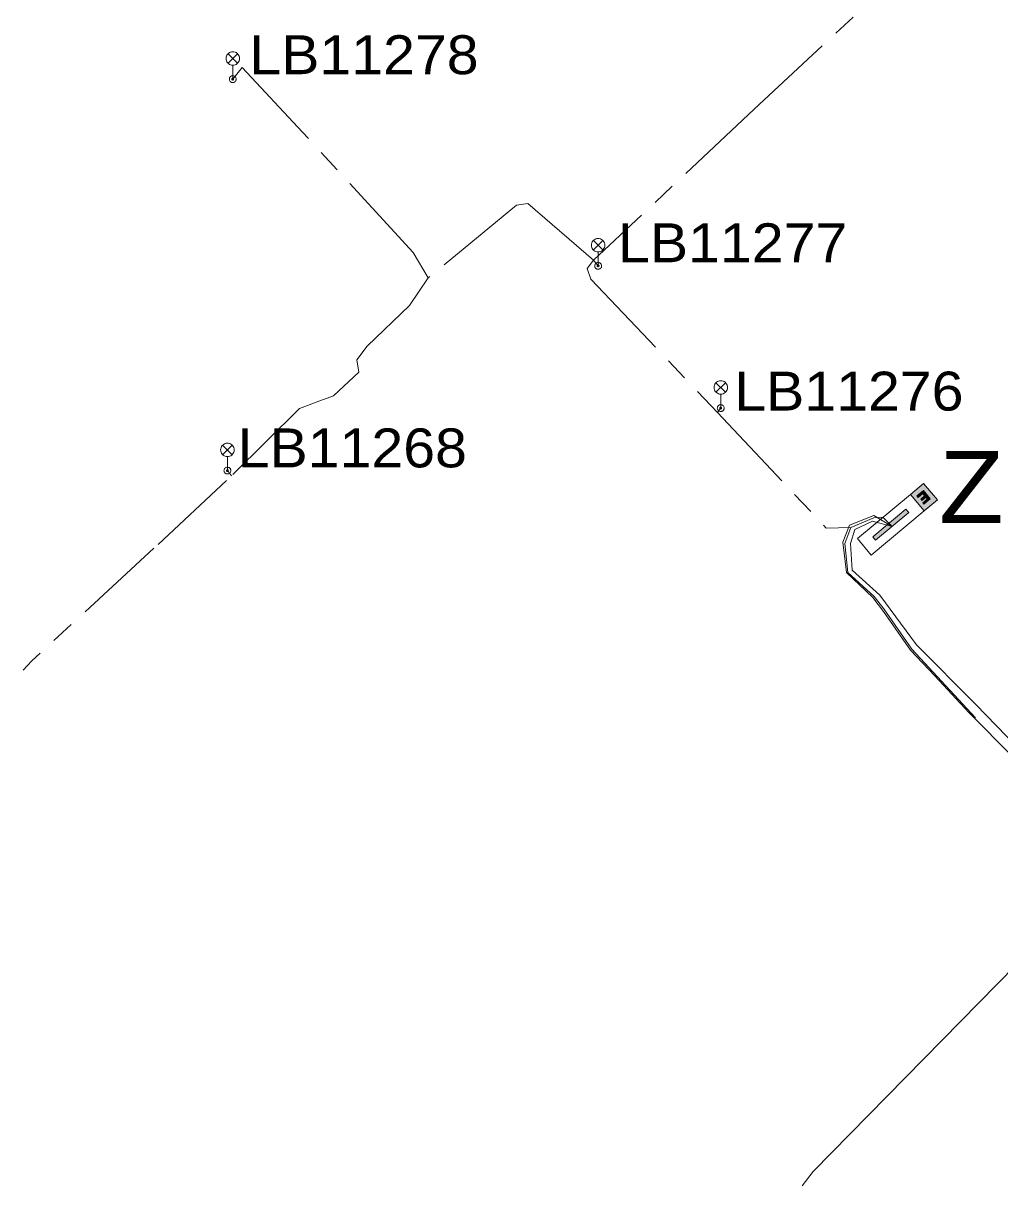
# Model space of a CAD drawing. Extents: x -688049 to -687261, y -973611 to -973038.
# Drawn here: x -687618.8 to -687564.4, y -973611.3 to -973546.5 of the extents above; entities that cross this region are included whole.
import ezdxf

# ---------------------------------------------------------------- set-up
doc = ezdxf.new("R2010")
doc.units = 0
doc.header["$LTSCALE"] = 0.87
doc.linetypes.add('LONG_DASH_SHORT_DASH', pattern=[9.9, 6, -1.2, 1.5, -1.2])
doc.layers.add('1', color=7, linetype='Continuous', lineweight=13)

msp = doc.modelspace()

# ---------------------------------------------------------------- hatches: boundary and pattern name
at = {"layer": '1'}
for points in [[(-687567.892, -973573.083), (-687568.629, -973573.698), (-687569.398, -973572.777), (-687568.661, -973572.162)], [(-687568.673, -973572.563), (-687568.289, -973573.023), (-687568.644, -973573.32), (-687568.708, -973573.244), (-687568.458, -973573.034), (-687568.542, -973572.933), (-687568.76, -973573.115), (-687568.823, -973573.038), (-687568.606, -973572.857), (-687568.708, -973572.734), (-687568.959, -973572.943), (-687569.029, -973572.859)], [(-687569.489, -973573.791), (-687571.332, -973575.329), (-687571.485, -973575.145), (-687569.643, -973573.607)]]:
    msp.add_hatch(color=256, dxfattribs=at).paths.add_polyline_path(points)

# ---------------------------------------------------------------- linework, layer by layer
for p, q in [((-687607.405, -973548.235), (-687606.875, -973548.765)), ((-687607.405, -973548.765), (-687606.875, -973548.235)), ((-687607.14, -973549.65), (-687607.14, -973548.875)), ((-687587.055, -973558.635), (-687586.525, -973559.165)), ((-687587.055, -973559.165), (-687586.525, -973558.635)), ((-687586.79, -973560.05), (-687586.79, -973559.275)), ((-687580.225, -973566.555), (-687579.695, -973567.085)), ((-687580.225, -973567.085), (-687579.695, -973566.555)), ((-687579.96, -973567.97), (-687579.96, -973567.195)), ((-687607.705, -973570.035), (-687607.175, -973570.565)), ((-687607.705, -973570.565), (-687607.175, -973570.035)), ((-687607.44, -973571.45), (-687607.44, -973570.675))]:
    msp.add_line(p, q, dxfattribs=at)
at = {"layer": '1', "linetype": 'LONG_DASH_SHORT_DASH'}
for p, q in [((-687587.04, -973559.73), (-687586.79, -973560.05)), ((-687587.04, -973559.73), (-687586.79, -973560.05)), ((-687587.04, -973559.73), (-687586.79, -973560.05)), ((-687587.04, -973559.73), (-687586.79, -973560.05)), ((-687587.04, -973559.73), (-687586.79, -973560.05)), ((-687587.04, -973559.73), (-687586.79, -973560.05)), ((-687587.04, -973559.73), (-687586.79, -973560.05)), ((-687587.04, -973559.73), (-687586.79, -973560.05)), ((-687580.14, -973568.22), (-687579.96, -973567.97)), ((-687580.14, -973568.22), (-687579.96, -973567.97)), ((-687580.14, -973568.22), (-687579.96, -973567.97)), ((-687580.14, -973568.22), (-687579.96, -973567.97)), ((-687580.14, -973568.22), (-687579.96, -973567.97)), ((-687580.14, -973568.22), (-687579.96, -973567.97)), ((-687580.14, -973568.22), (-687579.96, -973567.97)), ((-687607.44, -973571.45), (-687607.205, -973571.746)), ((-687607.44, -973571.45), (-687607.205, -973571.746)), ((-687607.44, -973571.45), (-687607.205, -973571.746)), ((-687607.44, -973571.45), (-687607.205, -973571.746)), ((-687607.44, -973571.45), (-687607.205, -973571.746)), ((-687607.44, -973571.45), (-687607.205, -973571.746)), ((-687607.44, -973571.45), (-687607.205, -973571.746)), ((-687607.44, -973571.45), (-687607.205, -973571.746))]:
    msp.add_line(p, q, dxfattribs=at)
for points in [[(-687568.01, -973541.92), (-687578.1, -973551.33), (-687587.04, -973559.73)], [(-687568.01, -973541.92), (-687578.1, -973551.33), (-687587.04, -973559.73)], [(-687568.01, -973541.92), (-687578.1, -973551.33), (-687587.04, -973559.73)], [(-687568.01, -973541.92), (-687578.1, -973551.33), (-687587.04, -973559.73)], [(-687568.01, -973541.92), (-687578.1, -973551.33), (-687587.04, -973559.73)], [(-687568.01, -973541.92), (-687578.1, -973551.33), (-687587.04, -973559.73)], [(-687568.01, -973541.92), (-687578.1, -973551.33), (-687587.04, -973559.73)], [(-687568.01, -973541.92), (-687578.1, -973551.33), (-687587.04, -973559.73)], [(-687596.25, -973560.71), (-687597.1, -973559.31), (-687603.25, -973552.6), (-687606.608, -973549.002), (-687607.14, -973549.65)], [(-687596.25, -973560.71), (-687597.1, -973559.31), (-687603.25, -973552.6), (-687606.608, -973549.002), (-687607.14, -973549.65)], [(-687596.25, -973560.71), (-687597.1, -973559.31), (-687603.25, -973552.6), (-687606.608, -973549.002), (-687607.14, -973549.65)], [(-687596.25, -973560.71), (-687597.1, -973559.31), (-687603.25, -973552.6), (-687606.608, -973549.002), (-687607.14, -973549.65)], [(-687596.25, -973560.71), (-687597.1, -973559.31), (-687603.25, -973552.6), (-687606.608, -973549.002), (-687607.14, -973549.65)], [(-687596.25, -973560.71), (-687597.1, -973559.31), (-687603.25, -973552.6), (-687606.608, -973549.002), (-687607.14, -973549.65)], [(-687596.25, -973560.71), (-687597.1, -973559.31), (-687603.25, -973552.6), (-687606.608, -973549.002), (-687607.14, -973549.65)], [(-687596.25, -973560.71), (-687597.1, -973559.31), (-687603.25, -973552.6), (-687606.608, -973549.002), (-687607.14, -973549.65)], [(-687587.04, -973559.73), (-687590.71, -973556.58), (-687591.33, -973556.67), (-687596.25, -973560.71)], [(-687587.04, -973559.73), (-687590.71, -973556.58), (-687591.33, -973556.67), (-687596.25, -973560.71)], [(-687587.04, -973559.73), (-687590.71, -973556.58), (-687591.33, -973556.67), (-687596.25, -973560.71)], [(-687587.04, -973559.73), (-687590.71, -973556.58), (-687591.33, -973556.67), (-687596.25, -973560.71)], [(-687587.04, -973559.73), (-687590.71, -973556.58), (-687591.33, -973556.67), (-687596.25, -973560.71)], [(-687587.04, -973559.73), (-687590.71, -973556.58), (-687591.33, -973556.67), (-687596.25, -973560.71)], [(-687587.04, -973559.73), (-687590.71, -973556.58), (-687591.33, -973556.67), (-687596.25, -973560.71)], [(-687587.04, -973559.73), (-687590.71, -973556.58), (-687591.33, -973556.67), (-687596.25, -973560.71)], [(-687587.04, -973559.73), (-687587.392, -973560.187), (-687587.19, -973560.79), (-687580.14, -973568.22)], [(-687587.04, -973559.73), (-687587.392, -973560.187), (-687587.19, -973560.79), (-687580.14, -973568.22), (-687579.96, -973567.97)], [(-687587.04, -973559.73), (-687587.392, -973560.187), (-687587.19, -973560.79), (-687580.14, -973568.22)], [(-687587.04, -973559.73), (-687587.392, -973560.187), (-687587.19, -973560.79), (-687580.14, -973568.22)], [(-687587.04, -973559.73), (-687587.392, -973560.187), (-687587.19, -973560.79), (-687580.14, -973568.22)], [(-687587.04, -973559.73), (-687587.392, -973560.187), (-687587.19, -973560.79), (-687580.14, -973568.22)], [(-687587.04, -973559.73), (-687587.392, -973560.187), (-687587.19, -973560.79), (-687580.14, -973568.22)], [(-687587.04, -973559.73), (-687587.392, -973560.187), (-687587.19, -973560.79), (-687580.14, -973568.22)], [(-687596.25, -973560.71), (-687597.3, -973562.26), (-687599.66, -973564.53), (-687600.23, -973565.28)], [(-687596.25, -973560.71), (-687597.3, -973562.26), (-687599.66, -973564.53), (-687600.23, -973565.28)], [(-687596.25, -973560.71), (-687597.3, -973562.26), (-687599.66, -973564.53), (-687600.23, -973565.28)], [(-687596.25, -973560.71), (-687597.3, -973562.26), (-687599.66, -973564.53), (-687600.23, -973565.28)], [(-687596.25, -973560.71), (-687597.3, -973562.26), (-687599.66, -973564.53), (-687600.23, -973565.28)], [(-687596.25, -973560.71), (-687597.3, -973562.26), (-687599.66, -973564.53), (-687600.23, -973565.28)], [(-687596.25, -973560.71), (-687597.3, -973562.26), (-687599.66, -973564.53), (-687600.23, -973565.28)], [(-687596.25, -973560.71), (-687597.3, -973562.26), (-687599.66, -973564.53), (-687600.23, -973565.28)], [(-687600.23, -973565.28), (-687600.11, -973565.97), (-687601.52, -973567.28), (-687602.29, -973567.57), (-687603.43, -973567.99), (-687607.48, -973572.01), (-687611.53, -973575.78), (-687618.34, -973582.05), (-687618.81, -973582.57)], [(-687600.23, -973565.28), (-687600.11, -973565.97), (-687601.52, -973567.28), (-687602.29, -973567.57), (-687603.43, -973567.99), (-687607.48, -973572.01), (-687611.53, -973575.78), (-687618.34, -973582.05), (-687618.81, -973582.57)], [(-687600.23, -973565.28), (-687600.11, -973565.97), (-687601.52, -973567.28), (-687602.29, -973567.57), (-687603.43, -973567.99), (-687607.48, -973572.01), (-687611.53, -973575.78), (-687618.34, -973582.05), (-687618.81, -973582.57)], [(-687600.23, -973565.28), (-687600.11, -973565.97), (-687601.52, -973567.28), (-687602.29, -973567.57), (-687603.43, -973567.99), (-687607.48, -973572.01), (-687611.53, -973575.78), (-687618.34, -973582.05), (-687618.81, -973582.57)], [(-687600.23, -973565.28), (-687600.11, -973565.97), (-687601.52, -973567.28), (-687602.29, -973567.57), (-687603.43, -973567.99), (-687607.48, -973572.01), (-687611.53, -973575.78), (-687618.34, -973582.05), (-687618.81, -973582.57)], [(-687600.23, -973565.28), (-687600.11, -973565.97), (-687601.52, -973567.28), (-687602.29, -973567.57), (-687603.43, -973567.99), (-687607.48, -973572.01), (-687611.53, -973575.78), (-687618.34, -973582.05), (-687618.81, -973582.57)], [(-687600.23, -973565.28), (-687600.11, -973565.97), (-687601.52, -973567.28), (-687602.29, -973567.57), (-687603.43, -973567.99), (-687607.48, -973572.01), (-687611.53, -973575.78), (-687618.34, -973582.05), (-687618.81, -973582.57)], [(-687600.23, -973565.28), (-687600.11, -973565.97), (-687601.52, -973567.28), (-687602.29, -973567.57), (-687603.43, -973567.99), (-687607.48, -973572.01), (-687611.53, -973575.78), (-687618.34, -973582.05), (-687618.81, -973582.57)], [(-687580.14, -973568.22), (-687574.08, -973574.65), (-687572.71, -973574.62), (-687571.44, -973574.08), (-687570.93, -973574.05), (-687570.41, -973574.56)], [(-687580.14, -973568.22), (-687574.08, -973574.65), (-687572.71, -973574.62), (-687571.44, -973574.08), (-687570.93, -973574.05), (-687570.41, -973574.56)], [(-687580.14, -973568.22), (-687574.08, -973574.65), (-687572.71, -973574.62), (-687571.44, -973574.08), (-687570.93, -973574.05), (-687570.41, -973574.56)], [(-687580.14, -973568.22), (-687574.08, -973574.65), (-687572.71, -973574.62), (-687571.44, -973574.08), (-687570.93, -973574.05), (-687570.41, -973574.56)], [(-687580.14, -973568.22), (-687574.08, -973574.65), (-687572.71, -973574.62), (-687571.44, -973574.08), (-687570.93, -973574.05), (-687570.41, -973574.56)], [(-687580.14, -973568.22), (-687574.08, -973574.65), (-687572.71, -973574.62), (-687571.44, -973574.08), (-687570.93, -973574.05), (-687570.41, -973574.56)], [(-687580.14, -973568.22), (-687574.08, -973574.65), (-687572.71, -973574.62), (-687571.44, -973574.08), (-687570.93, -973574.05), (-687570.41, -973574.56)], [(-687580.14, -973568.22), (-687574.08, -973574.65), (-687572.71, -973574.62), (-687571.44, -973574.08), (-687570.93, -973574.05), (-687570.41, -973574.56)], [(-687572.71, -973574.62), (-687573.05, -973575.52), (-687572.89, -973577.12), (-687571.42, -973578.47), (-687570.88, -973579.15), (-687569.32, -973581.39), (-687565.31, -973585.73)], [(-687572.71, -973574.62), (-687573.05, -973575.52), (-687572.89, -973577.12), (-687571.42, -973578.47), (-687570.88, -973579.15), (-687569.32, -973581.39), (-687565.31, -973585.73)], [(-687572.71, -973574.62), (-687573.05, -973575.52), (-687572.89, -973577.12), (-687571.42, -973578.47), (-687570.88, -973579.15), (-687569.32, -973581.39), (-687565.31, -973585.73)], [(-687572.71, -973574.62), (-687573.05, -973575.52), (-687572.89, -973577.12), (-687571.42, -973578.47), (-687570.88, -973579.15), (-687569.32, -973581.39), (-687565.31, -973585.73)], [(-687572.71, -973574.62), (-687573.05, -973575.52), (-687572.89, -973577.12), (-687571.42, -973578.47), (-687570.88, -973579.15), (-687569.32, -973581.39), (-687565.31, -973585.73)], [(-687572.71, -973574.62), (-687573.05, -973575.52), (-687572.89, -973577.12), (-687571.42, -973578.47), (-687570.88, -973579.15), (-687569.32, -973581.39), (-687565.31, -973585.73)], [(-687572.71, -973574.62), (-687573.05, -973575.52), (-687572.89, -973577.12), (-687571.42, -973578.47), (-687570.88, -973579.15), (-687569.32, -973581.39), (-687565.31, -973585.73)], [(-687572.71, -973574.62), (-687573.05, -973575.52), (-687572.89, -973577.12), (-687571.42, -973578.47), (-687570.88, -973579.15), (-687569.32, -973581.39), (-687565.31, -973585.73)]]:
    msp.add_lwpolyline(points, dxfattribs=at)
at = {"layer": '1'}
for points in [[(-687606.765, -973548.5), (-687606.771, -973548.435), (-687606.788, -973548.372), (-687606.815, -973548.312), (-687606.853, -973548.259), (-687606.899, -973548.213), (-687606.952, -973548.175), (-687607.012, -973548.148), (-687607.075, -973548.131), (-687607.14, -973548.125), (-687607.205, -973548.131), (-687607.268, -973548.148), (-687607.328, -973548.175), (-687607.381, -973548.213), (-687607.427, -973548.259), (-687607.465, -973548.312), (-687607.492, -973548.372), (-687607.509, -973548.435), (-687607.515, -973548.5), (-687607.509, -973548.565), (-687607.492, -973548.628), (-687607.465, -973548.688), (-687607.427, -973548.741), (-687607.381, -973548.787), (-687607.328, -973548.825), (-687607.268, -973548.852), (-687607.205, -973548.869), (-687607.14, -973548.875), (-687607.075, -973548.869), (-687607.012, -973548.852), (-687606.952, -973548.825), (-687606.899, -973548.787), (-687606.853, -973548.741), (-687606.815, -973548.688), (-687606.788, -973548.628), (-687606.771, -973548.565)], [(-687606.95, -973549.65), (-687606.953, -973549.617), (-687606.961, -973549.585), (-687606.975, -973549.555), (-687606.994, -973549.528), (-687607.018, -973549.504), (-687607.045, -973549.485), (-687607.075, -973549.471), (-687607.107, -973549.463), (-687607.14, -973549.46), (-687607.173, -973549.463), (-687607.205, -973549.471), (-687607.235, -973549.485), (-687607.262, -973549.504), (-687607.286, -973549.528), (-687607.305, -973549.555), (-687607.319, -973549.585), (-687607.327, -973549.617), (-687607.33, -973549.65), (-687607.327, -973549.683), (-687607.319, -973549.715), (-687607.305, -973549.745), (-687607.286, -973549.772), (-687607.262, -973549.796), (-687607.235, -973549.815), (-687607.205, -973549.829), (-687607.173, -973549.837), (-687607.14, -973549.84), (-687607.107, -973549.837), (-687607.075, -973549.829), (-687607.045, -973549.815), (-687607.018, -973549.796), (-687606.994, -973549.772), (-687606.975, -973549.745), (-687606.961, -973549.715), (-687606.953, -973549.683)], [(-687607.09, -973549.65), (-687607.091, -973549.641), (-687607.093, -973549.633), (-687607.097, -973549.625), (-687607.102, -973549.618), (-687607.108, -973549.612), (-687607.115, -973549.607), (-687607.123, -973549.603), (-687607.131, -973549.601), (-687607.14, -973549.6), (-687607.149, -973549.601), (-687607.157, -973549.603), (-687607.165, -973549.607), (-687607.172, -973549.612), (-687607.178, -973549.618), (-687607.183, -973549.625), (-687607.187, -973549.633), (-687607.189, -973549.641), (-687607.19, -973549.65), (-687607.189, -973549.659), (-687607.187, -973549.667), (-687607.183, -973549.675), (-687607.178, -973549.682), (-687607.172, -973549.688), (-687607.165, -973549.693), (-687607.157, -973549.697), (-687607.149, -973549.699), (-687607.14, -973549.7), (-687607.131, -973549.699), (-687607.123, -973549.697), (-687607.115, -973549.693), (-687607.108, -973549.688), (-687607.102, -973549.682), (-687607.097, -973549.675), (-687607.093, -973549.667), (-687607.091, -973549.659)], [(-687586.415, -973558.9), (-687586.421, -973558.835), (-687586.438, -973558.772), (-687586.465, -973558.712), (-687586.503, -973558.659), (-687586.549, -973558.613), (-687586.602, -973558.575), (-687586.662, -973558.548), (-687586.725, -973558.531), (-687586.79, -973558.525), (-687586.855, -973558.531), (-687586.918, -973558.548), (-687586.978, -973558.575), (-687587.031, -973558.613), (-687587.077, -973558.659), (-687587.115, -973558.712), (-687587.142, -973558.772), (-687587.159, -973558.835), (-687587.165, -973558.9), (-687587.159, -973558.965), (-687587.142, -973559.028), (-687587.115, -973559.088), (-687587.077, -973559.141), (-687587.031, -973559.187), (-687586.978, -973559.225), (-687586.918, -973559.252), (-687586.855, -973559.269), (-687586.79, -973559.275), (-687586.725, -973559.269), (-687586.662, -973559.252), (-687586.602, -973559.225), (-687586.549, -973559.187), (-687586.503, -973559.141), (-687586.465, -973559.088), (-687586.438, -973559.028), (-687586.421, -973558.965)], [(-687586.6, -973560.05), (-687586.603, -973560.017), (-687586.611, -973559.985), (-687586.625, -973559.955), (-687586.644, -973559.928), (-687586.668, -973559.904), (-687586.695, -973559.885), (-687586.725, -973559.871), (-687586.757, -973559.863), (-687586.79, -973559.86), (-687586.823, -973559.863), (-687586.855, -973559.871), (-687586.885, -973559.885), (-687586.912, -973559.904), (-687586.936, -973559.928), (-687586.955, -973559.955), (-687586.969, -973559.985), (-687586.977, -973560.017), (-687586.98, -973560.05), (-687586.977, -973560.083), (-687586.969, -973560.115), (-687586.955, -973560.145), (-687586.936, -973560.172), (-687586.912, -973560.196), (-687586.885, -973560.215), (-687586.855, -973560.229), (-687586.823, -973560.237), (-687586.79, -973560.24), (-687586.757, -973560.237), (-687586.725, -973560.229), (-687586.695, -973560.215), (-687586.668, -973560.196), (-687586.644, -973560.172), (-687586.625, -973560.145), (-687586.611, -973560.115), (-687586.603, -973560.083)], [(-687586.74, -973560.05), (-687586.741, -973560.041), (-687586.743, -973560.033), (-687586.747, -973560.025), (-687586.752, -973560.018), (-687586.758, -973560.012), (-687586.765, -973560.007), (-687586.773, -973560.003), (-687586.781, -973560.001), (-687586.79, -973560), (-687586.799, -973560.001), (-687586.807, -973560.003), (-687586.815, -973560.007), (-687586.822, -973560.012), (-687586.828, -973560.018), (-687586.833, -973560.025), (-687586.837, -973560.033), (-687586.839, -973560.041), (-687586.84, -973560.05), (-687586.839, -973560.059), (-687586.837, -973560.067), (-687586.833, -973560.075), (-687586.828, -973560.082), (-687586.822, -973560.088), (-687586.815, -973560.093), (-687586.807, -973560.097), (-687586.799, -973560.099), (-687586.79, -973560.1), (-687586.781, -973560.099), (-687586.773, -973560.097), (-687586.765, -973560.093), (-687586.758, -973560.088), (-687586.752, -973560.082), (-687586.747, -973560.075), (-687586.743, -973560.067), (-687586.741, -973560.059)], [(-687579.585, -973566.82), (-687579.591, -973566.755), (-687579.608, -973566.692), (-687579.635, -973566.633), (-687579.673, -973566.579), (-687579.719, -973566.533), (-687579.772, -973566.495), (-687579.832, -973566.468), (-687579.895, -973566.451), (-687579.96, -973566.445), (-687580.025, -973566.451), (-687580.088, -973566.468), (-687580.148, -973566.495), (-687580.201, -973566.533), (-687580.247, -973566.579), (-687580.285, -973566.633), (-687580.312, -973566.692), (-687580.329, -973566.755), (-687580.335, -973566.82), (-687580.329, -973566.885), (-687580.312, -973566.948), (-687580.285, -973567.008), (-687580.247, -973567.061), (-687580.201, -973567.107), (-687580.148, -973567.145), (-687580.088, -973567.172), (-687580.025, -973567.189), (-687579.96, -973567.195), (-687579.895, -973567.189), (-687579.832, -973567.172), (-687579.772, -973567.145), (-687579.719, -973567.107), (-687579.673, -973567.061), (-687579.635, -973567.008), (-687579.608, -973566.948), (-687579.591, -973566.885)], [(-687579.77, -973567.97), (-687579.773, -973567.937), (-687579.781, -973567.905), (-687579.795, -973567.875), (-687579.814, -973567.848), (-687579.838, -973567.824), (-687579.865, -973567.805), (-687579.895, -973567.791), (-687579.927, -973567.783), (-687579.96, -973567.78), (-687579.993, -973567.783), (-687580.025, -973567.791), (-687580.055, -973567.805), (-687580.082, -973567.824), (-687580.106, -973567.848), (-687580.125, -973567.875), (-687580.139, -973567.905), (-687580.147, -973567.937), (-687580.15, -973567.97), (-687580.147, -973568.003), (-687580.139, -973568.035), (-687580.125, -973568.065), (-687580.106, -973568.092), (-687580.082, -973568.116), (-687580.055, -973568.135), (-687580.025, -973568.149), (-687579.993, -973568.157), (-687579.96, -973568.16), (-687579.927, -973568.157), (-687579.895, -973568.149), (-687579.865, -973568.135), (-687579.838, -973568.116), (-687579.814, -973568.092), (-687579.795, -973568.065), (-687579.781, -973568.035), (-687579.773, -973568.003)], [(-687579.91, -973567.97), (-687579.911, -973567.961), (-687579.913, -973567.953), (-687579.917, -973567.945), (-687579.922, -973567.938), (-687579.928, -973567.932), (-687579.935, -973567.927), (-687579.943, -973567.923), (-687579.951, -973567.921), (-687579.96, -973567.92), (-687579.969, -973567.921), (-687579.977, -973567.923), (-687579.985, -973567.927), (-687579.992, -973567.932), (-687579.998, -973567.938), (-687580.003, -973567.945), (-687580.007, -973567.953), (-687580.009, -973567.961), (-687580.01, -973567.97), (-687580.009, -973567.979), (-687580.007, -973567.987), (-687580.003, -973567.995), (-687579.998, -973568.002), (-687579.992, -973568.008), (-687579.985, -973568.013), (-687579.977, -973568.017), (-687579.969, -973568.019), (-687579.96, -973568.02), (-687579.951, -973568.019), (-687579.943, -973568.017), (-687579.935, -973568.013), (-687579.928, -973568.008), (-687579.922, -973568.002), (-687579.917, -973567.995), (-687579.913, -973567.987), (-687579.911, -973567.979)], [(-687607.065, -973570.3), (-687607.071, -973570.235), (-687607.088, -973570.172), (-687607.115, -973570.112), (-687607.153, -973570.059), (-687607.199, -973570.013), (-687607.253, -973569.975), (-687607.312, -973569.948), (-687607.375, -973569.931), (-687607.44, -973569.925), (-687607.505, -973569.931), (-687607.568, -973569.948), (-687607.628, -973569.975), (-687607.681, -973570.013), (-687607.727, -973570.059), (-687607.765, -973570.112), (-687607.792, -973570.172), (-687607.809, -973570.235), (-687607.815, -973570.3), (-687607.809, -973570.365), (-687607.792, -973570.428), (-687607.765, -973570.487), (-687607.727, -973570.541), (-687607.681, -973570.587), (-687607.628, -973570.625), (-687607.568, -973570.652), (-687607.505, -973570.669), (-687607.44, -973570.675), (-687607.375, -973570.669), (-687607.312, -973570.652), (-687607.253, -973570.625), (-687607.199, -973570.587), (-687607.153, -973570.541), (-687607.115, -973570.487), (-687607.088, -973570.428), (-687607.071, -973570.365)], [(-687607.25, -973571.45), (-687607.253, -973571.417), (-687607.261, -973571.385), (-687607.275, -973571.355), (-687607.294, -973571.328), (-687607.318, -973571.304), (-687607.345, -973571.285), (-687607.375, -973571.271), (-687607.407, -973571.263), (-687607.44, -973571.26), (-687607.473, -973571.263), (-687607.505, -973571.271), (-687607.535, -973571.285), (-687607.562, -973571.304), (-687607.586, -973571.328), (-687607.605, -973571.355), (-687607.619, -973571.385), (-687607.627, -973571.417), (-687607.63, -973571.45), (-687607.627, -973571.483), (-687607.619, -973571.515), (-687607.605, -973571.545), (-687607.586, -973571.572), (-687607.562, -973571.596), (-687607.535, -973571.615), (-687607.505, -973571.629), (-687607.473, -973571.637), (-687607.44, -973571.64), (-687607.407, -973571.637), (-687607.375, -973571.629), (-687607.345, -973571.615), (-687607.318, -973571.596), (-687607.294, -973571.572), (-687607.275, -973571.545), (-687607.261, -973571.515), (-687607.253, -973571.483)], [(-687607.39, -973571.45), (-687607.391, -973571.441), (-687607.393, -973571.433), (-687607.397, -973571.425), (-687607.402, -973571.418), (-687607.408, -973571.412), (-687607.415, -973571.407), (-687607.423, -973571.403), (-687607.431, -973571.401), (-687607.44, -973571.4), (-687607.449, -973571.401), (-687607.457, -973571.403), (-687607.465, -973571.407), (-687607.472, -973571.412), (-687607.478, -973571.418), (-687607.483, -973571.425), (-687607.487, -973571.433), (-687607.489, -973571.441), (-687607.49, -973571.45), (-687607.489, -973571.459), (-687607.487, -973571.467), (-687607.483, -973571.475), (-687607.478, -973571.482), (-687607.472, -973571.488), (-687607.465, -973571.493), (-687607.457, -973571.497), (-687607.449, -973571.499), (-687607.44, -973571.5), (-687607.431, -973571.499), (-687607.423, -973571.497), (-687607.415, -973571.493), (-687607.408, -973571.488), (-687607.402, -973571.482), (-687607.397, -973571.475), (-687607.393, -973571.467), (-687607.391, -973571.459)], [(-687567.892, -973573.083), (-687568.629, -973573.698), (-687569.398, -973572.777), (-687568.661, -973572.162)], [(-687567.892, -973573.083), (-687568.629, -973573.698), (-687569.398, -973572.777), (-687568.661, -973572.162)], [(-687568.673, -973572.563), (-687568.289, -973573.023), (-687568.644, -973573.32), (-687568.708, -973573.244), (-687568.458, -973573.034), (-687568.542, -973572.933), (-687568.76, -973573.115), (-687568.823, -973573.038), (-687568.606, -973572.857), (-687568.708, -973572.734), (-687568.959, -973572.943), (-687569.029, -973572.859)], [(-687569.489, -973573.791), (-687571.332, -973575.329), (-687571.485, -973575.145), (-687569.643, -973573.607)]]:
    msp.add_lwpolyline(points, close=True, dxfattribs=at)
for points in [[(-687512.242, -973562.244), (-687513.198, -973563.185), (-687513.014, -973563.421), (-687513.139, -973563.788), (-687513.139, -973564.053), (-687521.25, -973569.673), (-687531.507, -973572.146), (-687537.665, -973575.239), (-687557.082, -973591.297), (-687558.661, -973591.432), (-687559.419, -973591.073), (-687564.028, -973586.264), (-687565.766, -973584.462), (-687569.052, -973581.162), (-687571.096, -973578.384), (-687572.639, -973577), (-687572.732, -973575.503), (-687572.487, -973574.726), (-687571.502, -973574.263), (-687570.41, -973574.56)], [(-687568.629, -973573.698), (-687571.577, -973576.159), (-687572.346, -973575.238), (-687569.398, -973572.777)], [(-687575.42, -973611.28), (-687574.806, -973610.489), (-687558.387, -973593.76), (-687558.722, -973592.406), (-687566.143, -973584.922), (-687568.035, -973582.887), (-687569.398, -973581.455), (-687570.886, -973579.299), (-687571.488, -973578.516), (-687572.957, -973577.125), (-687573.154, -973575.44), (-687572.785, -973574.494), (-687571.43, -973573.953), (-687570.41, -973574.56)]]:
    msp.add_lwpolyline(points, dxfattribs=at)

# ---------------------------------------------------------------- texts
at = {"layer": '1', "width": 1.1}
for s, height, p in [('LB11278', 2.168, (-687606.216, -973549.374)), ('LB11277', 2.168, (-687585.678, -973559.848)), ('LB11276', 2.168, (-687579.206, -973568.109)), ('LB11268', 2.168, (-687606.867, -973571.271)), ('ZM LB156', 4, (-687567.797, -973574.364))]:
    msp.add_text(s, height=height, dxfattribs=at).set_placement(p)

doc.saveas('drawing.dxf')
